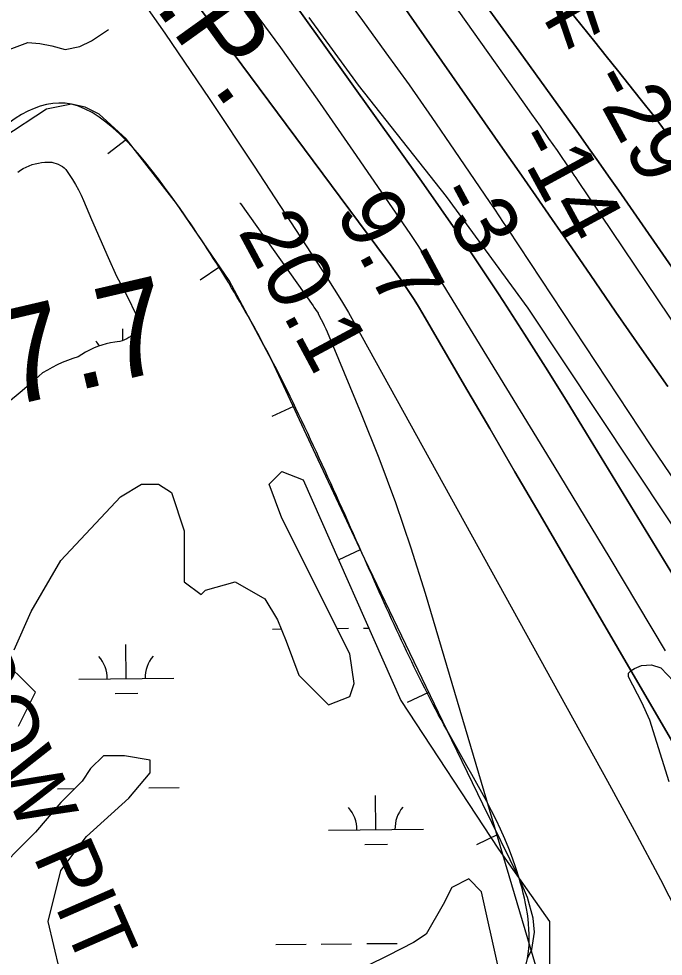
# Model space of a CAD drawing. Extents: x 3625074 to 3663148, y 511451 to 537151.
# Drawn here: x 3629922 to 3630601, y 529469 to 530458 of the extents above; entities that cross this region are included whole.
import ezdxf

# ---------------------------------------------------------------- set-up
doc = ezdxf.new("R2010")
doc.units = 0
for name, color, linetype in [('V-BORW-IDEN', 7, 'Continuous'), ('V-BORW-LINE', 7, 'Continuous'), ('V-CHAN-NAID', 7, 'Continuous'), ('V-RIVR-EDGE', 7, 'Continuous'), ('V-RIVR-RANG', 7, 'Continuous'), ('V-SITE-VEGE', 7, 'Continuous'), ('V-SURV-IDEN', 7, 'Continuous'), ('V-TOPO-DPTH', 7, 'Continuous'), ('V-TOPO-MINR', 7, 'Continuous'), ('V-TOPO-SHOR', 7, 'Continuous'), ('V-TOPO-WATR', 7, 'Continuous'), ('V-TOPO-WATR-IDEN', 7, 'Continuous'), ('V-WETL-SWMP', 7, 'Continuous')]:
    doc.layers.add(name, color=color, linetype=linetype)

msp = doc.modelspace()

# ---------------------------------------------------------------- linework, layer by layer
at = {"layer": 'V-BORW-LINE'}
for p, q in [((3630035.28, 530330.44), (3630015.55, 530315.08)), ((3630133.58, 530196.03), (3630112.95, 530181.92)), ((3630211.08, 530048.76), (3630188.4, 530038.23)), ((3630281.52, 529897.78), (3630258.88, 529887.19)), ((3630353.49, 529747.53), (3630330.96, 529736.71)), ((3630426.37, 529597.72), (3630403.92, 529586.71))]:
    msp.add_line(p, q, dxfattribs=at)
msp.add_lwpolyline([(3630457.52, 529466.91), (3630462.18, 529476.34), (3630465.04, 529494.72), (3630463.64, 529509.39), (3630457.56, 529531.42), (3630448.89, 529551.79), (3630410.63, 529629.8), (3630372.53, 529707.89), (3630329.34, 529797.83), (3630286.2, 529887.79), (3630237.19, 529992.51), (3630188.48, 530097.42), (3630143.49, 530181.54), (3630087.84, 530262.91), (3630034.82, 530331.03), (3630006.32, 530356.86), (3629991.82, 530364.53), (3629977.24, 530367.48), (3629951.01, 530362.44), (3629904.84, 530332.23)], dxfattribs=at)
msp.add_spline([(3629776.87, 528883.45), (3629740.76, 528986.47), (3629698.11, 529091.63), (3629672.48, 529247.92), (3629619.57, 529371.62), (3629549.92, 529540.41), (3629488.31, 529757.35), (3629449.75, 529913.89), (3629450.07, 529995.99), (3629570.92, 530100.01), (3629762.32, 530198.97), (3629977.24, 530367.48), (3630087.84, 530262.91), (3630188.48, 530097.42), (3630286.2, 529887.79), (3630372.53, 529707.89), (3630448.89, 529551.79), (3630457.52, 529466.91), (3630326.2, 529316.58), (3630161.53, 529154.2), (3629969.27, 528959.65), (3629893.23, 528888.46), (3629848.54, 528865.17), (3629806.55, 528857.3), (3629776.87, 528883.45)], degree=3, dxfattribs=at)
at = {"layer": 'V-RIVR-EDGE'}
msp.add_lwpolyline([(3630227.17, 530459.08), (3630279.22, 530387.52), (3630371.98, 530270.22), (3630458.14, 530152.35), (3630642.95, 529873.94)], dxfattribs=at)
at = {"layer": 'V-SITE-VEGE'}
msp.add_lwpolyline([(3630606.92, 529653.2), (3630586.43, 529718.21), (3630578.18, 529736.78), (3630564.2, 529763.98), (3630564.1, 529767.66), (3630566.68, 529770.58), (3630570.3, 529772.72), (3630577.56, 529775.97), (3630588.37, 529776.66), (3630598.06, 529773.24), (3630611.49, 529759.5)], dxfattribs=at)
at = {"layer": 'V-TOPO-DPTH'}
for points in [[(3630716.89, 529512.76), (3630497.39, 529889.23), (3630470.9, 529934.66), (3630444.41, 529980.1), (3630417.93, 530025.53), (3630391.45, 530070.97), (3630347.42, 530146.52), (3630342.88, 530154.13), (3630338.22, 530161.68), (3630333.41, 530169.12), (3630328.5, 530176.5), (3630323.46, 530183.79), (3630318.36, 530191.04), (3630313.18, 530198.24), (3630307.93, 530205.39), (3629995.08, 530627.05)], [(3630605.5, 530069.9), (3630578.02, 530109.11), (3630550.71, 530148.44), (3630523.53, 530187.85), (3630501.04, 530220.62), (3630483.7, 530245.82), (3630466.33, 530271), (3630448.9, 530296.15), (3630431.45, 530321.28), (3630250.26, 530581.43)], [(3630250.26, 530581.43), (3630431.45, 530321.28), (3630448.9, 530296.15), (3630466.33, 530271), (3630483.7, 530245.82), (3630501.04, 530220.62), (3630523.53, 530187.85), (3630550.71, 530148.44), (3630578.02, 530109.11), (3630605.5, 530069.9)], [(3630662.6, 529786.42), (3630519.9, 530020.53), (3630498.36, 530055.51), (3630476.62, 530090.36), (3630454.55, 530125.02), (3630432.28, 530159.54), (3630426.41, 530168.55), (3630406.73, 530198.34), (3630386.79, 530227.95), (3630366.47, 530257.31), (3630345.89, 530286.49), (3630142.59, 530570.85)], [(3630142.59, 530570.85), (3630345.89, 530286.49), (3630366.47, 530257.31), (3630386.79, 530227.95), (3630406.73, 530198.34), (3630426.41, 530168.55), (3630432.28, 530159.54), (3630454.55, 530125.02), (3630476.62, 530090.36), (3630498.36, 530055.51), (3630519.9, 530020.53), (3630662.6, 529786.42)], [(3630406.82, 530481.83), (3630448.88, 530423.58), (3630511.39, 530336.59), (3630522.02, 530321.71), (3630532.6, 530306.8), (3630543.11, 530291.84), (3630553.56, 530276.84), (3630622.48, 530177.38)], [(3630622.48, 530177.38), (3630553.56, 530276.84), (3630543.11, 530291.84), (3630532.6, 530306.8), (3630522.02, 530321.71), (3630511.39, 530336.59), (3630448.88, 530423.58), (3630406.82, 530481.83)], [(3630494.31, 530475.89), (3630513.7, 530451.67), (3630528.63, 530433.13), (3630540.62, 530418.22), (3630552.58, 530403.28), (3630564.5, 530388.31), (3630576.39, 530373.32), (3630591.96, 530353.64), (3630595.96, 530348.42), (3630599.86, 530343.12), (3630603.59, 530337.7)], [(3630603.59, 530337.7), (3630599.86, 530343.12), (3630595.96, 530348.42), (3630591.96, 530353.64), (3630576.39, 530373.32), (3630564.5, 530388.31), (3630552.58, 530403.28), (3630540.62, 530418.22), (3630528.63, 530433.13), (3630513.7, 530451.67), (3630494.31, 530475.89)]]:
    msp.add_lwpolyline(points, dxfattribs=at)
at = {"layer": 'V-TOPO-MINR'}
for points in [[(3630006.71, 530999.32), (3630452.79, 530369.93), (3630461.83, 530357.13), (3630470.85, 530344.3), (3630479.82, 530331.44), (3630488.77, 530318.57), (3630502.7, 530298.44), (3630504.65, 530295.61), (3630506.59, 530292.77), (3630508.53, 530289.92), (3630510.45, 530287.07), (3630655.05, 530071.94)], [(3629924.55, 530941.8), (3630283.91, 530455.61), (3630308.55, 530421.85), (3630332.92, 530387.89), (3630356.87, 530353.65), (3630380.54, 530319.21), (3630417.97, 530264.05), (3630422.72, 530257.03), (3630427.44, 530250), (3630432.14, 530242.95), (3630436.82, 530235.9), (3630587.65, 530007.48), (3630635.66, 529936.34)], [(3629995.08, 530627.05), (3630307.93, 530205.39), (3630313.18, 530198.24), (3630318.36, 530191.04), (3630323.46, 530183.79), (3630328.5, 530176.5), (3630333.41, 530169.12), (3630338.22, 530161.68), (3630342.88, 530154.13), (3630347.42, 530146.52), (3630391.45, 530070.97), (3630417.93, 530025.53), (3630444.41, 529980.1), (3630470.9, 529934.66), (3630497.39, 529889.23), (3630716.89, 529512.76)], [(3630250.26, 530581.43), (3630431.45, 530321.28), (3630448.9, 530296.15), (3630466.33, 530271), (3630483.7, 530245.82), (3630501.04, 530220.62), (3630523.53, 530187.85), (3630550.71, 530148.44), (3630578.02, 530109.11), (3630605.5, 530069.9)], [(3630027.22, 530511.79), (3630075.57, 530442.51), (3630122.93, 530372.55), (3630169.64, 530302.15), (3630246.25, 530184.9), (3630254.03, 530172.7), (3630261.63, 530160.38), (3630268.95, 530147.91), (3630276.08, 530135.32), (3630542.05, 529653.78), (3630570.11, 529602.16), (3630597.69, 529550.29), (3630624.55, 529498.05)], [(3630157.87, 530481.32), (3630197.33, 530427.44), (3630235.99, 530373), (3630274.12, 530318.17), (3630333.54, 530231.38), (3630341.48, 530219.6), (3630349.29, 530207.75), (3630356.92, 530195.78), (3630364.44, 530183.73), (3630485.53, 529986.26), (3630544.5, 529889.02), (3630602.81, 529791.38)], [(3630406.82, 530481.83), (3630448.88, 530423.58), (3630511.39, 530336.59), (3630522.02, 530321.71), (3630532.6, 530306.8), (3630543.11, 530291.84), (3630553.56, 530276.84), (3630622.48, 530177.38)], [(3630494.31, 530475.89), (3630513.7, 530451.67), (3630528.63, 530433.13), (3630540.62, 530418.22), (3630552.58, 530403.28), (3630564.5, 530388.31), (3630576.39, 530373.32), (3630591.96, 530353.64), (3630595.96, 530348.42), (3630599.86, 530343.12), (3630603.59, 530337.7)], [(3630154.68, 530263.06), (3630154.71, 530263.12), (3630155.02, 530263.15), (3630155.46, 530262.99), (3630231.82, 530155.02), (3630232.72, 530153.73), (3630234.48, 530151.11), (3630237.03, 530147.12), (3630237.25, 530146.71), (3630240.39, 530140.64), (3630242.03, 530137.38), (3630243.61, 530134.09), (3630245.11, 530130.77), (3630246.56, 530127.42), (3630282.43, 530041.29), (3630301.01, 529994.58), (3630318.59, 529947.52), (3630334.66, 529899.92), (3630349.72, 529851.96), (3630522.37, 529269.8)]]:
    msp.add_lwpolyline(points, dxfattribs=at)
at = {"layer": 'V-TOPO-SHOR'}
msp.add_lwpolyline([(3629174.25, 530373.82), (3629307.44, 530170.6), (3629362.54, 530104.63), (3629371.25, 530093.63), (3629378.41, 530088.2), (3629388.24, 530088.45), (3629410.36, 530101.67), (3629638.14, 530252.29), (3629795.71, 530349.1), (3629911.68, 530425.17), (3629931.15, 530432.7), (3629943.82, 530431.63), (3629956.52, 530429.15), (3629970.67, 530425.31), (3629986.03, 530428.52), (3629998.51, 530434.46), (3630016.46, 530446.17)], dxfattribs=at)
at = {"layer": 'V-TOPO-WATR'}
msp.add_lwpolyline([(3630142.59, 530570.85), (3630345.89, 530286.49), (3630366.47, 530257.31), (3630386.79, 530227.95), (3630406.73, 530198.34), (3630426.41, 530168.55), (3630432.28, 530159.54), (3630454.55, 530125.02), (3630476.62, 530090.36), (3630498.36, 530055.51), (3630519.9, 530020.53), (3630662.6, 529786.42)], dxfattribs=at)
at = {"layer": 'V-WETL-SWMP'}
for p, q in [((3630031.44, 530118.55), (3630031.32, 530130.69)), ((3630189.05, 529814.31), (3630198.18, 529814.41)), ((3630257, 529815), (3630269.05, 529815.12)), ((3630285.05, 529815.28), (3630290.34, 529815.33)), ((3630034.98, 529762.02), (3630034.62, 529798.02)), ((3629984.98, 529761.52), (3630084.98, 529762.52)), ((3630023.14, 529746.47), (3630047.13, 529746.71)), ((3629962.73, 529645.86), (3629980.81, 529646.04)), ((3630058.73, 529646.82), (3630090.73, 529647.14)), ((3630298.03, 529602.79), (3630297.67, 529638.79)), ((3630248.03, 529602.29), (3630348.02, 529603.29)), ((3630286.18, 529587.24), (3630310.18, 529587.48)), ((3630288.39, 529482.62), (3630320.39, 529482.94)), ((3630336.39, 529483.1), (3630336.39, 529483.1)), ((3630192.39, 529481.66), (3630224.39, 529481.98)), ((3630240.39, 529482.14), (3630272.39, 529482.46))]:
    msp.add_line(p, q, dxfattribs=at)
for points in [[(3629920.88, 530295.94), (3629923.66, 530297.89), (3629926.56, 530299.66), (3629929.57, 530301.24), (3629932.67, 530302.62), (3629935.86, 530303.8), (3629939.12, 530304.76), (3629942.43, 530305.52), (3629945.79, 530306.06), (3629949.17, 530306.38), (3629951.6, 530306.56), (3629954.03, 530306.52), (3629956.45, 530306.27), (3629958.84, 530305.79), (3629961.17, 530305.1), (3629963.43, 530304.2), (3629965.6, 530303.09), (3629967.66, 530301.79), (3629969.59, 530300.32), (3629971.38, 530298.67), (3629974.93, 530293.49), (3629978.31, 530288.2), (3629981.51, 530282.8), (3629984.54, 530277.29), (3629987.38, 530271.69), (3629990.03, 530266), (3629998.43, 530245.9), (3630007.01, 530225.88), (3630015.78, 530205.95), (3630024.74, 530186.09), (3630031.39, 530173.91), (3630037.73, 530161.57), (3630043.78, 530149.09), (3630044.71, 530146.96), (3630045.43, 530144.74), (3630045.93, 530142.47), (3630046.22, 530140.17), (3630046.28, 530137.84), (3630046.12, 530135.52), (3630045.74, 530133.23), (3630045.14, 530130.98), (3630044.33, 530128.8), (3630043.31, 530126.71), (3630042.1, 530124.72), (3630040.04, 530123.07), (3630037.85, 530121.59), (3630035.54, 530120.29), (3630033.14, 530119.17), (3630030.66, 530118.26), (3630028.11, 530117.55), (3630025.51, 530117.04), (3630022.88, 530116.75), (3630018.27, 530115.95), (3630013.71, 530114.9), (3630009.21, 530113.62), (3630004.78, 530112.1), (3630000.44, 530110.36), (3629996.2, 530108.39), (3629992.06, 530106.21), (3629988.04, 530103.81), (3629984.16, 530101.21), (3629978.57, 530099.41), (3629973.06, 530097.4), (3629967.62, 530095.18), (3629962.27, 530092.77), (3629957.02, 530090.15), (3629951.87, 530087.34), (3629946.82, 530084.34), (3629935.06, 530073.84), (3629923.15, 530063.52), (3629911.08, 530053.38)], [(3629966.17, 529886.49), (3630028.82, 529953.61), (3630051.2, 529967.04), (3630069.1, 529967.04), (3630082.52, 529958.09), (3630095.95, 529917.81), (3630095.95, 529890.96), (3630095.95, 529864.11), (3630113.85, 529850.68), (3630118.33, 529855.16), (3630149.65, 529864.11), (3630180.98, 529846.21), (3630194.41, 529823.83), (3630203.36, 529801.45), (3630216.78, 529765.65), (3630248.11, 529734.33), (3630270.48, 529743.28), (3630274.96, 529756.7), (3630270.48, 529788.03), (3630198.88, 529931.24), (3630185.46, 529967.04), (3630198.88, 529980.47), (3630221.26, 529971.52), (3630324.19, 529738.8), (3630427.12, 529582.17), (3630480.82, 529506.09), (3630480.82, 529452.38)], [(3629916.94, 529792.51), (3629934.84, 529832.78), (3629966.17, 529886.49)], [(3629921.41, 529711.95), (3629939.31, 529747.75), (3629930.36, 529756.7), (3629925.89, 529761.18), (3629912.46, 529774.6)], [(3629970.64, 529430.01), (3629952.74, 529506.09), (3629966.17, 529559.79), (3629993.02, 529595.59), (3630037.77, 529635.87), (3630060.15, 529662.72), (3630060.15, 529676.15), (3630033.29, 529680.62), (3630010.92, 529680.62), (3629997.49, 529667.2), (3629988.54, 529653.77)], [(3629988.54, 529653.77), (3629966.17, 529631.4), (3629939.31, 529600.07), (3629890.09, 529550.84)], [(3630427.12, 529456.86), (3630409.22, 529537.41), (3630395.79, 529550.84), (3630377.89, 529541.89), (3630368.94, 529523.99), (3630351.04, 529492.66), (3630337.61, 529483.71), (3630310.76, 529470.29), (3630266.01, 529447.91)]]:
    msp.add_lwpolyline(points, dxfattribs=at)
for centre, start, end in [((3629976.43, 530094.61), 30.95936, 41.34685), ((3629979.74, 529761.94), 359.8032, 41.34685), ((3630090.22, 529763.05), 139.80319, 181.34685), ((3630242.78, 529602.71), 359.8032, 41.34685), ((3630353.26, 529603.82), 139.80319, 181.34685)]:
    msp.add_arc(centre, 35.25, start, end, dxfattribs=at)

# ---------------------------------------------------------------- texts
at = {"layer": 'V-BORW-IDEN'}
msp.add_text('BORROW PIT', height=64, rotation=293.63492, dxfattribs=at).set_placement((3629768.67, 529958.27))
at = {"layer": 'V-CHAN-NAID'}
msp.add_text(' #3 (111.4)', height=100, rotation=29.66672, dxfattribs=at).set_placement((3630461.64, 530402.67))
at = {"layer": 'V-RIVR-RANG'}
for s, rotation, p in [('-29', 298.52453, (3630520.31, 530392.43)), ('-14', 298.52453, (3630440.39, 530330.06)), ('9.7', 298.23833, (3630254.65, 530253.88)), ('-3', 298.23833, (3630358.23, 530272.37)), ('20.1', 298.23833, (3630152.07, 530233.54))]:
    msp.add_text(s, height=67, rotation=rotation, dxfattribs=at).set_placement(p)
at = {"layer": 'V-SURV-IDEN'}
msp.add_text('162+87.7', height=100, rotation=13.17218, dxfattribs=at).set_placement((3629543.73, 529962.62))
at = {"layer": 'V-TOPO-WATR-IDEN'}
msp.add_text('L.W.R.P.', height=83, rotation=305.68069, dxfattribs=at).set_placement((3629884.37, 530720.75))

doc.saveas('drawing.dxf')
